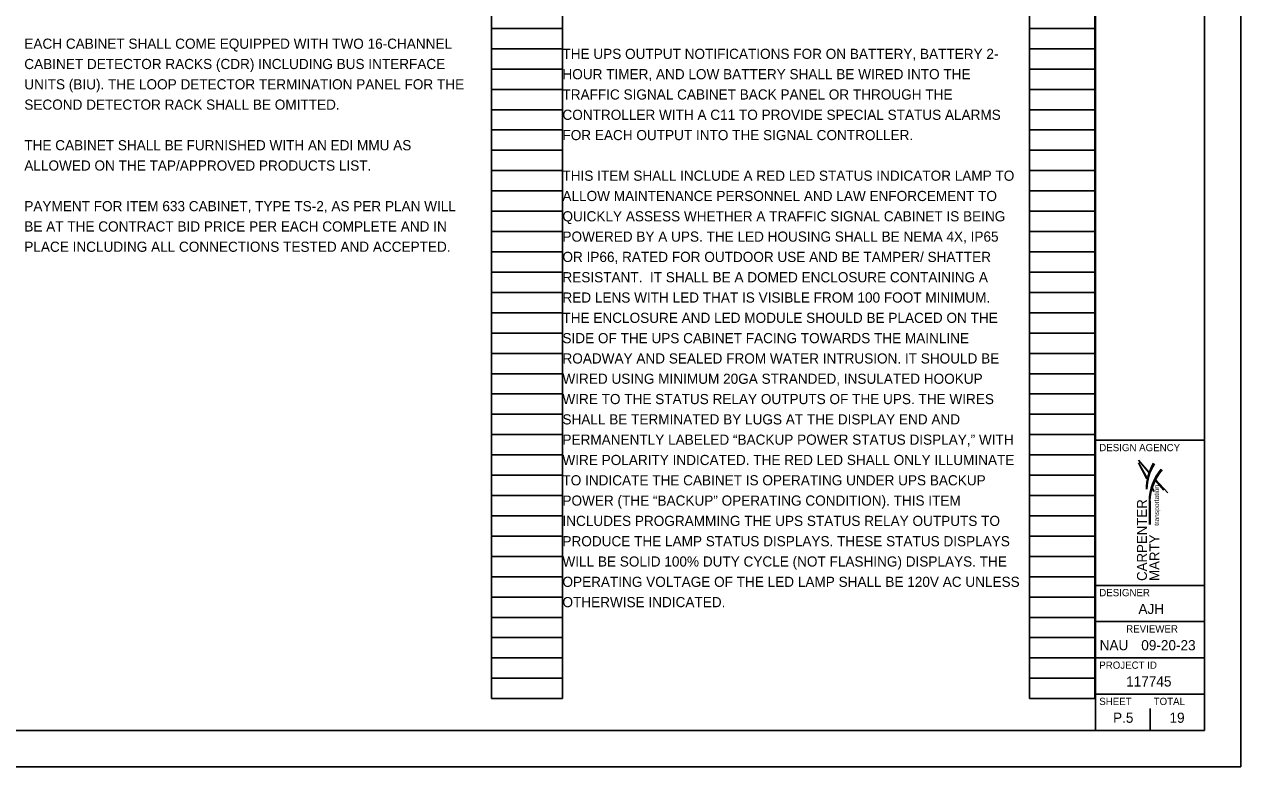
# Model space of a CAD drawing. Extents: x -57 to 90, y -15 to 48.
# Drawn here: x 72.92 to 89.69, y 25.51 to 35.74 of the extents above; entities that cross this region are included whole.
import ezdxf

# ---------------------------------------------------------------- set-up
doc = ezdxf.new("R2010")
doc.units = 0
for name, color, linetype in [('SH_Border', 7, 'Continuous'), ('SH_Cut_Line', 7, 'Continuous'), ('SH_Data', 7, 'Continuous'), ('SH_Text', 7, 'Continuous')]:
    doc.layers.add(name, color=color, linetype=linetype)

msp = doc.modelspace()

# ---------------------------------------------------------------- linework, layer by layer
at = {"layer": 'SH_Border'}
for p, q in [((87.688, 26.006), (87.688, 47.006)), ((87.688, 30.006), (89.188, 30.006)), ((87.688, 28.006), (89.188, 28.006)), ((87.688, 27.506), (89.188, 27.506)), ((87.688, 27.006), (89.188, 27.006)), ((87.688, 26.506), (89.188, 26.506))]:
    msp.add_line(p, q, dxfattribs=at)
msp.add_lwpolyline([(57.188, 47.006), (89.188, 47.006), (89.188, 26.006), (57.188, 26.006)], close=True, dxfattribs=at)
at = {"layer": 'SH_Cut_Line'}
msp.add_lwpolyline([(55.688, 25.506), (89.688, 25.506), (89.688, 47.506), (55.688, 47.506)], close=True, dxfattribs=at)
at = {"layer": 'SH_Data'}
for p, q in [((79.356, 26.445), (79.356, 46.605)), ((80.336, 26.445), (80.336, 46.605)), ((86.776, 26.445), (86.776, 46.605)), ((87.676, 26.445), (87.676, 46.605)), ((79.356, 35.685), (80.336, 35.685)), ((86.776, 35.685), (87.676, 35.685)), ((79.356, 35.405), (80.336, 35.405)), ((86.776, 35.405), (87.676, 35.405)), ((79.356, 35.125), (80.336, 35.125)), ((86.776, 35.125), (87.676, 35.125)), ((79.356, 34.845), (80.336, 34.845)), ((86.776, 34.845), (87.676, 34.845)), ((79.356, 34.565), (80.336, 34.565)), ((86.776, 34.565), (87.676, 34.565)), ((79.356, 34.285), (80.336, 34.285)), ((86.776, 34.285), (87.676, 34.285)), ((79.356, 34.005), (80.336, 34.005)), ((86.776, 34.005), (87.676, 34.005)), ((79.356, 33.725), (80.336, 33.725)), ((86.776, 33.725), (87.676, 33.725)), ((79.356, 33.445), (80.336, 33.445)), ((86.776, 33.445), (87.676, 33.445)), ((79.356, 33.165), (80.336, 33.165)), ((86.776, 33.165), (87.676, 33.165)), ((79.356, 32.885), (80.336, 32.885)), ((86.776, 32.885), (87.676, 32.885)), ((79.356, 32.605), (80.336, 32.605)), ((86.776, 32.605), (87.676, 32.605)), ((79.356, 32.325), (80.336, 32.325)), ((86.776, 32.325), (87.676, 32.325)), ((79.356, 32.045), (80.336, 32.045)), ((86.776, 32.045), (87.676, 32.045)), ((79.356, 31.765), (80.336, 31.765)), ((86.776, 31.765), (87.676, 31.765)), ((79.356, 31.485), (80.336, 31.485)), ((86.776, 31.485), (87.676, 31.485)), ((79.356, 31.205), (80.336, 31.205)), ((86.776, 31.205), (87.676, 31.205)), ((79.356, 30.925), (80.336, 30.925)), ((86.776, 30.925), (87.676, 30.925)), ((79.356, 30.645), (80.336, 30.645)), ((86.776, 30.645), (87.676, 30.645)), ((79.356, 30.365), (80.336, 30.365)), ((86.776, 30.365), (87.676, 30.365)), ((79.356, 30.085), (80.336, 30.085)), ((86.776, 30.085), (87.676, 30.085)), ((79.356, 29.805), (80.336, 29.805)), ((86.776, 29.805), (87.676, 29.805)), ((79.356, 29.525), (80.336, 29.525)), ((86.776, 29.525), (87.676, 29.525)), ((79.356, 29.245), (80.336, 29.245)), ((86.776, 29.245), (87.676, 29.245)), ((79.356, 28.965), (80.336, 28.965)), ((86.776, 28.965), (87.676, 28.965)), ((88.438, 29.006), (88.438, 29.006)), ((79.356, 28.685), (80.336, 28.685)), ((86.776, 28.685), (87.676, 28.685)), ((79.356, 28.405), (80.336, 28.405)), ((86.776, 28.405), (87.676, 28.405)), ((79.356, 28.125), (80.336, 28.125)), ((86.776, 28.125), (87.676, 28.125)), ((79.356, 27.845), (80.336, 27.845)), ((86.776, 27.845), (87.676, 27.845)), ((79.356, 27.565), (80.336, 27.565)), ((86.776, 27.565), (87.676, 27.565)), ((79.356, 27.285), (80.336, 27.285)), ((86.776, 27.285), (87.676, 27.285)), ((79.356, 27.005), (80.336, 27.005)), ((86.776, 27.005), (87.676, 27.005)), ((79.356, 26.725), (80.336, 26.725)), ((86.776, 26.725), (87.676, 26.725)), ((79.356, 26.445), (80.336, 26.445)), ((86.776, 26.445), (87.676, 26.445)), ((88.063, 26.181), (88.063, 26.181)), ((88.438, 26.006), (88.438, 26.306))]:
    msp.add_line(p, q, dxfattribs=at)
at = {"layer": 'SH_Text'}
for p, q in [((88.397, 29.482), (88.278, 29.697)), ((88.496, 29.299), (88.467, 29.351)), ((88.628, 29.318), (88.51, 29.456)), ((88.515, 29.467), (88.682, 29.281)), ((88.487, 29.306), (88.466, 29.345)), ((88.431, 28.843), (88.431, 29.169)), ((88.438, 28.843), (88.438, 29.169))]:
    msp.add_line(p, q, dxfattribs=at)
for points in [[(88.422, 29.569), (88.277, 29.731)], [(88.277, 29.731), (88.42, 29.563)], [(88.397, 29.482), (88.278, 29.697)], [(88.278, 29.697), (88.395, 29.476)]]:
    msp.add_lwpolyline(points, dxfattribs=at)
for centre, radius, start, end in [((89.108, 29.325), 0.721, 149.5704, 179.5529), ((89.049, 29.327), 0.654, 147.1423, 179.6525), ((89.101, 29.169), 0.671, 139.2898, 180.0106), ((89.109, 29.153), 0.672, 138.5126, 178.6075)]:
    msp.add_arc(centre, radius, start, end, dxfattribs=at)

# ---------------------------------------------------------------- texts
at = {"layer": 'SH_Data'}
for s, height, p in [('DESIGN AGENCY', 0.1, (87.738, 29.856)), ('DESIGNER', 0.1, (87.738, 27.856)), ('AJH', 0.14, (88.278, 27.611)), ('REVIEWER', 0.1, (88.109, 27.356)), ('NAU', 0.14, (87.743, 27.111)), ('09-20-23', 0.14, (88.317, 27.111)), ('PROJECT ID', 0.1, (87.738, 26.856)), ('117745', 0.14, (88.109, 26.611)), ('SHEET', 0.1, (87.738, 26.356)), ('TOTAL', 0.1, (88.488, 26.356)), ('P.5', 0.14, (87.928, 26.111)), ('19', 0.14, (88.706, 26.111))]:
    msp.add_text(s, height=height, dxfattribs=at).set_placement(p)
at = {"layer": 'SH_Text'}
for s, p in [('EACH CABINET SHALL COME EQUIPPED WITH TWO 16-CHANNEL', (72.916, 35.405)), ('THE UPS OUTPUT NOTIFICATIONS FOR ON BATTERY, BATTERY 2-', (80.336, 35.265)), ('CABINET DETECTOR RACKS (CDR) INCLUDING BUS INTERFACE', (72.916, 35.125)), ('HOUR TIMER, AND LOW BATTERY SHALL BE WIRED INTO THE ', (80.336, 34.985)), ('UNITS (BIU). THE LOOP DETECTOR TERMINATION PANEL FOR THE', (72.916, 34.845)), ('TRAFFIC SIGNAL CABINET BACK PANEL OR THROUGH THE ', (80.336, 34.705)), ('SECOND DETECTOR RACK SHALL BE OMITTED.', (72.916, 34.565)), ('CONTROLLER WITH A C11 TO PROVIDE SPECIAL STATUS ALARMS ', (80.336, 34.425)), ('FOR EACH OUTPUT INTO THE SIGNAL CONTROLLER. ', (80.336, 34.145)), ('THE CABINET SHALL BE FURNISHED WITH AN EDI MMU AS', (72.916, 34.005)), ('ALLOWED ON THE TAP/APPROVED PRODUCTS LIST.', (72.916, 33.725)), ('THIS ITEM SHALL INCLUDE A RED LED STATUS INDICATOR LAMP TO ', (80.336, 33.585)), ('ALLOW MAINTENANCE PERSONNEL AND LAW ENFORCEMENT TO ', (80.336, 33.305)), ('PAYMENT FOR ITEM 633 CABINET, TYPE TS-2, AS PER PLAN WILL', (72.916, 33.165)), ('QUICKLY ASSESS WHETHER A TRAFFIC SIGNAL CABINET IS BEING ', (80.336, 33.025)), ('BE AT THE CONTRACT BID PRICE PER EACH COMPLETE AND IN', (72.916, 32.885)), ('POWERED BY A UPS. THE LED HOUSING SHALL BE NEMA 4X, IP65 ', (80.336, 32.745)), ('PLACE INCLUDING ALL CONNECTIONS TESTED AND ACCEPTED.', (72.916, 32.605)), ('OR IP66, RATED FOR OUTDOOR USE AND BE TAMPER/ SHATTER ', (80.336, 32.465)), ('RESISTANT.  IT SHALL BE A DOMED ENCLOSURE CONTAINING A ', (80.336, 32.185)), ('RED LENS WITH LED THAT IS VISIBLE FROM 100 FOOT MINIMUM. ', (80.336, 31.905)), ('THE ENCLOSURE AND LED MODULE SHOULD BE PLACED ON THE ', (80.336, 31.625)), ('SIDE OF THE UPS CABINET FACING TOWARDS THE MAINLINE ', (80.336, 31.345)), ('ROADWAY AND SEALED FROM WATER INTRUSION. IT SHOULD BE ', (80.336, 31.065)), ('WIRED USING MINIMUM 20GA STRANDED, INSULATED HOOKUP ', (80.336, 30.785)), ('WIRE TO THE STATUS RELAY OUTPUTS OF THE UPS. THE WIRES ', (80.336, 30.505)), ('SHALL BE TERMINATED BY LUGS AT THE DISPLAY END AND ', (80.336, 30.225)), ('PERMANENTLY LABELED “BACKUP POWER STATUS DISPLAY,” WITH ', (80.336, 29.945)), ('WIRE POLARITY INDICATED. THE RED LED SHALL ONLY ILLUMINATE ', (80.336, 29.665)), ('TO INDICATE THE CABINET IS OPERATING UNDER UPS BACKUP ', (80.336, 29.385)), ('POWER (THE “BACKUP” OPERATING CONDITION). THIS ITEM ', (80.336, 29.105)), ('INCLUDES PROGRAMMING THE UPS STATUS RELAY OUTPUTS TO ', (80.336, 28.825)), ('PRODUCE THE LAMP STATUS DISPLAYS. THESE STATUS DISPLAYS ', (80.336, 28.545)), ('WILL BE SOLID 100% DUTY CYCLE (NOT FLASHING) DISPLAYS. THE ', (80.336, 28.265)), ('OPERATING VOLTAGE OF THE LED LAMP SHALL BE 120V AC UNLESS ', (80.336, 27.985)), ('OTHERWISE INDICATED.', (80.336, 27.705))]:
    msp.add_text(s, height=0.14, dxfattribs=at).set_placement(p)
for s, height, p in [('transportation', 0.06649, (88.561, 28.829)), ('CARPENTER ', 0.1367, (88.395, 28.067)), ('MARTY', 0.1367, (88.567, 28.067))]:
    msp.add_text(s, height=height, rotation=90, dxfattribs=at).set_placement(p)

doc.saveas('drawing.dxf')
